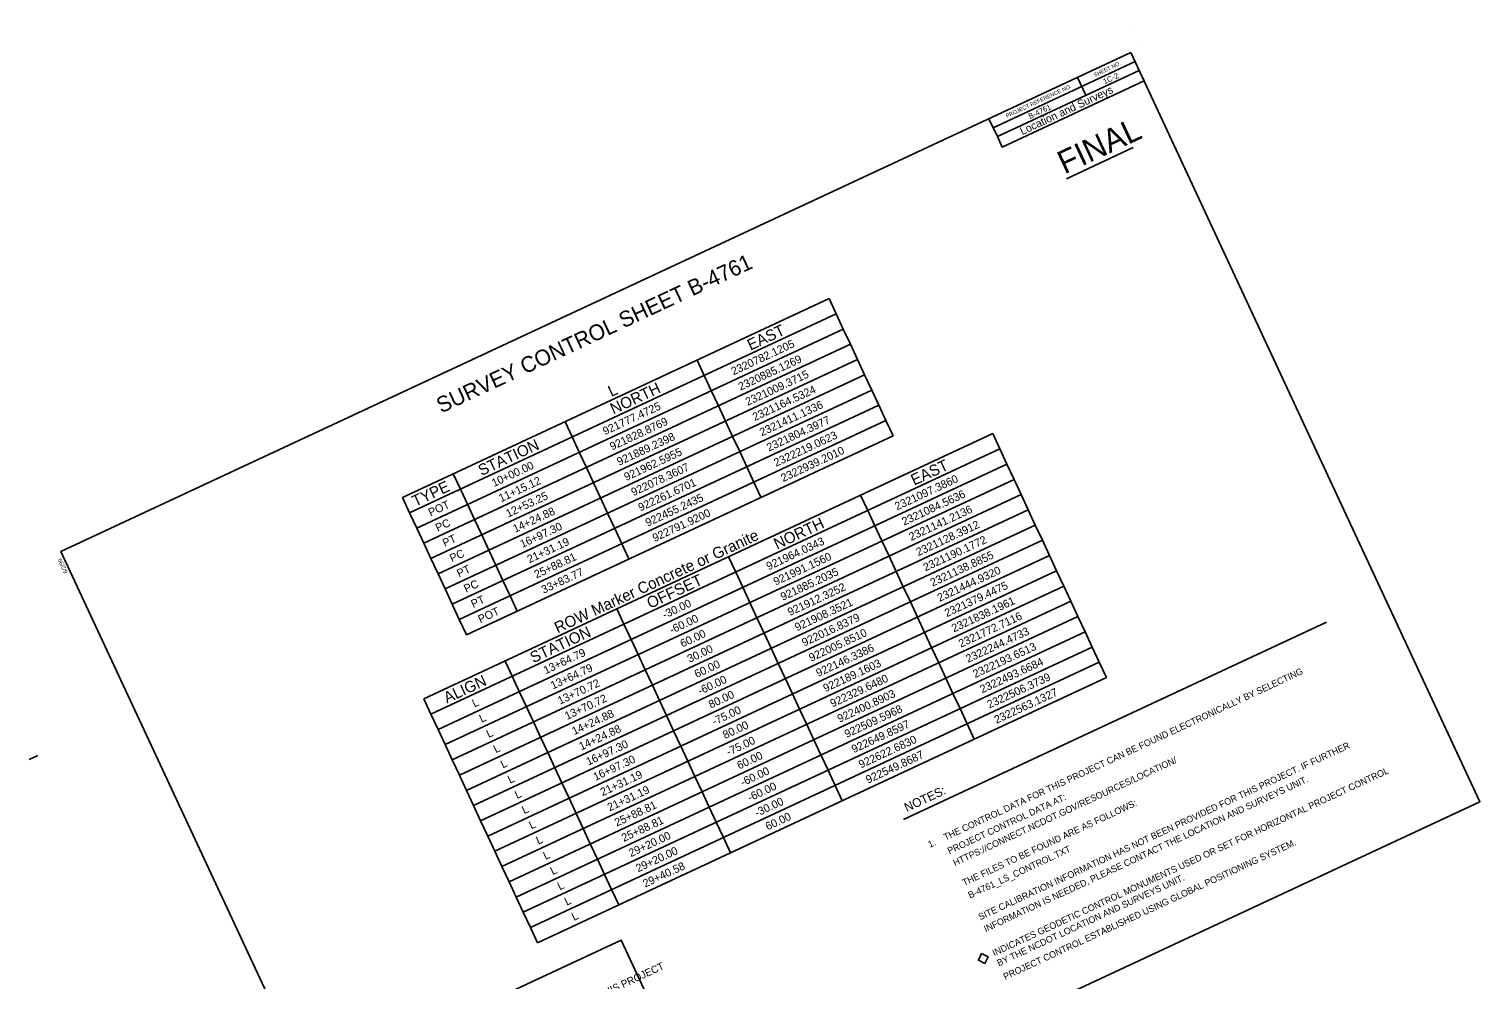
# Model space of a CAD drawing. Extents: x 2319517 to 2322650, y 921860 to 925282.
# Drawn here: x 2319517 to 2322650, y 923230 to 925282 of the extents above; entities that cross this region are included whole.
import ezdxf

# ---------------------------------------------------------------- set-up
doc = ezdxf.new("R2010")
doc.units = 0
for name, color, linetype in [('CTL Sheet Border CELL', 7, 'Continuous'), ('CTL Sheet Datum Description CELL', 7, 'Continuous'), ('CTL Sheet Notes CELL', 7, 'Continuous'), ('CTL Sheet Table Cell', 7, 'Continuous'), ('CTL Sheet Text', 7, 'Continuous'), ('CTL Supplemental Horizontal and Vertical CELL', 7, 'Continuous'), ('Sheet Sticker Preliminary CELL', 7, 'Continuous')]:
    doc.layers.add(name, color=color, linetype=linetype)

msp = doc.modelspace()

# ---------------------------------------------------------------- linework, layer by layer
at = {"layer": 'CTL Sheet Border CELL'}
for p, q in [((2321904.2, 925282.4), (2321904.2, 925282.4)), ((2321913.4, 925244.7), (2321913.4, 925244.7)), ((2321913.4, 925244.7), (2321913.4, 925244.7)), ((2321597, 925068.8), (2321905, 925212.4)), ((2321780.5, 925177.9), (2321798.5, 925139.4)), ((2321589.7, 925088.9), (2321607.7, 925050.4)), ((2319517.5, 923706.1), (2319536.7, 923715))]:
    msp.add_line(p, q, dxfattribs=at)
for points in [[(2321896, 925231.7), (2319586.4, 924155.2), (2320340, 922538.5), (2322649.5, 923615.1)], [(2321607.7, 925050.4), (2321913.9, 925193.2), (2321924.5, 925170.5), (2321618.2, 925027.8)]]:
    msp.add_lwpolyline(points, close=True, dxfattribs=at)
at = {"layer": 'CTL Sheet Datum Description CELL'}
msp.add_lwpolyline([(2320359.3, 922575.6), (2320153.7, 923016.8), (2320795.8, 923316.1), (2321001.5, 922874.9)], close=True, dxfattribs=at)
at = {"layer": 'CTL Sheet Notes CELL'}
msp.add_line((2321405.2, 923576.9), (2322318.1, 924002.4), dxfattribs=at)
at = {"layer": 'CTL Sheet Table Cell'}
for p, q in [((2320323.6, 924271.5), (2321244.6, 924700.8)), ((2321244.6, 924700.8), (2321259.9, 924667.9)), ((2320339, 924238.6), (2321259.9, 924667.9)), ((2321259.9, 924667.9), (2321275.2, 924635)), ((2320354.3, 924205.7), (2321275.2, 924635)), ((2321275.2, 924635), (2321290.6, 924602.1)), ((2320369.6, 924172.8), (2321290.6, 924602.1)), ((2321290.6, 924602.1), (2321305.9, 924569.2)), ((2320385, 924140), (2321305.9, 924569.2)), ((2320959.5, 924567.9), (2320974.8, 924535)), ((2321305.9, 924569.2), (2321321.2, 924536.3)), ((2320400.3, 924107.1), (2321321.2, 924536.3)), ((2320974.8, 924535), (2320990.2, 924502.1)), ((2321321.2, 924536.3), (2321336.6, 924503.4)), ((2320415.6, 924074.2), (2321336.6, 924503.4)), ((2320990.2, 924502.1), (2321005.5, 924469.2)), ((2321336.6, 924503.4), (2321351.9, 924470.5)), ((2320431, 924041.3), (2321351.9, 924470.5)), ((2321005.5, 924469.2), (2321020.8, 924436.4)), ((2321351.9, 924470.5), (2321367.2, 924437.7)), ((2320446.3, 924008.4), (2321367.2, 924437.7)), ((2320674.5, 924435), (2320689.8, 924402.2)), ((2321020.8, 924436.4), (2321036.2, 924403.5)), ((2321367.2, 924437.7), (2321382.5, 924404.8)), ((2320369.8, 923836.9), (2321597.7, 924409.3)), ((2320461.6, 923975.5), (2321382.5, 924404.8)), ((2321597.7, 924409.3), (2321613, 924376.4)), ((2320385.1, 923804.1), (2321613, 924376.4)), ((2320689.8, 924402.2), (2320705.1, 924369.3)), ((2321036.2, 924403.5), (2321051.5, 924370.6)), ((2321613, 924376.4), (2321628.3, 924343.5)), ((2320400.4, 923771.2), (2321628.3, 924343.5)), ((2320705.1, 924369.3), (2320720.5, 924336.4)), ((2321051.5, 924370.6), (2321066.8, 924337.7)), ((2321628.3, 924343.5), (2321643.7, 924310.6)), ((2320415.7, 923738.3), (2321643.7, 924310.6)), ((2320433.3, 924322.6), (2320448.6, 924289.7)), ((2320720.5, 924336.4), (2320735.8, 924303.5)), ((2321066.8, 924337.7), (2321082.2, 924304.8)), ((2321643.7, 924310.6), (2321659, 924277.7)), ((2320448.6, 924289.7), (2320463.9, 924256.8)), ((2320735.8, 924303.5), (2320751.1, 924270.6)), ((2321082.2, 924304.8), (2321097.5, 924271.9)), ((2320323.6, 924271.5), (2320339, 924238.6)), ((2320431.1, 923705.4), (2321659, 924277.7)), ((2320463.9, 924256.8), (2320479.3, 924223.9)), ((2320751.1, 924270.6), (2320766.5, 924237.7)), ((2321312.6, 924276.4), (2321327.9, 924243.5)), ((2321659, 924277.7), (2321674.3, 924244.9)), ((2320339, 924238.6), (2320354.3, 924205.7)), ((2320446.4, 923672.5), (2321674.3, 924244.9)), ((2320479.3, 924223.9), (2320494.6, 924191.1)), ((2320766.5, 924237.7), (2320781.8, 924204.8)), ((2321327.9, 924243.5), (2321343.3, 924210.7)), ((2321674.3, 924244.9), (2321689.6, 924212)), ((2320354.3, 924205.7), (2320369.6, 924172.8)), ((2320461.7, 923639.6), (2321689.6, 924212)), ((2320494.6, 924191.1), (2320509.9, 924158.2)), ((2320781.8, 924204.8), (2320797.1, 924171.9)), ((2321343.3, 924210.7), (2321358.6, 924177.8)), ((2321689.6, 924212), (2321705, 924179.1)), ((2320369.6, 924172.8), (2320385, 924140)), ((2320477.1, 923606.7), (2321705, 924179.1)), ((2320509.9, 924158.2), (2320525.3, 924125.3)), ((2320797.1, 924171.9), (2320812.4, 924139)), ((2321358.6, 924177.8), (2321373.9, 924144.9)), ((2321705, 924179.1), (2321720.3, 924146.2)), ((2320385, 924140), (2320400.3, 924107.1)), ((2320492.4, 923573.8), (2321720.3, 924146.2)), ((2320525.3, 924125.3), (2320540.6, 924092.4)), ((2321027.6, 924143.6), (2321042.9, 924110.7)), ((2321373.9, 924144.9), (2321389.3, 924112)), ((2321720.3, 924146.2), (2321735.6, 924113.3)), ((2320400.3, 924107.1), (2320415.6, 924074.2)), ((2320507.7, 923540.9), (2321735.6, 924113.3)), ((2320540.6, 924092.4), (2320555.9, 924059.5)), ((2321042.9, 924110.7), (2321058.2, 924077.8)), ((2321389.3, 924112), (2321404.6, 924079.1)), ((2321735.6, 924113.3), (2321751, 924080.4)), ((2320415.6, 924074.2), (2320431, 924041.3)), ((2320523.1, 923508), (2321751, 924080.4)), ((2320555.9, 924059.5), (2320571.2, 924026.6)), ((2321058.2, 924077.8), (2321073.6, 924044.9)), ((2321404.6, 924079.1), (2321419.9, 924046.2)), ((2321751, 924080.4), (2321766.3, 924047.5)), ((2320431, 924041.3), (2320446.3, 924008.4)), ((2320538.4, 923475.2), (2321766.3, 924047.5)), ((2320786.4, 924031.1), (2320801.7, 923998.3)), ((2321073.6, 924044.9), (2321088.9, 924012)), ((2321419.9, 924046.2), (2321435.3, 924013.3)), ((2321766.3, 924047.5), (2321781.6, 924014.6)), ((2320446.3, 924008.4), (2320461.6, 923975.5)), ((2320553.7, 923442.3), (2321781.6, 924014.6)), ((2320801.7, 923998.3), (2320817, 923965.4)), ((2321088.9, 924012), (2321104.2, 923979.1)), ((2321435.3, 924013.3), (2321450.6, 923980.4)), ((2321781.6, 924014.6), (2321797, 923981.7)), ((2320569.1, 923409.4), (2321797, 923981.7)), ((2320817, 923965.4), (2320832.4, 923932.5)), ((2321104.2, 923979.1), (2321119.5, 923946.2)), ((2321450.6, 923980.4), (2321465.9, 923947.5)), ((2321797, 923981.7), (2321812.3, 923948.8)), ((2320584.4, 923376.5), (2321812.3, 923948.8)), ((2321119.5, 923946.2), (2321134.9, 923913.3)), ((2321465.9, 923947.5), (2321481.2, 923914.6)), ((2321812.3, 923948.8), (2321827.6, 923915.9)), ((2320545.2, 923918.7), (2320560.5, 923885.8)), ((2320599.7, 923343.6), (2321827.6, 923915.9)), ((2320832.4, 923932.5), (2320847.7, 923899.6)), ((2321134.9, 923913.3), (2321150.2, 923880.4)), ((2321481.2, 923914.6), (2321496.6, 923881.8)), ((2321827.6, 923915.9), (2321843, 923883.1)), ((2320560.5, 923885.8), (2320575.8, 923852.9)), ((2320615, 923310.7), (2321843, 923883.1)), ((2320847.7, 923899.6), (2320863, 923866.7)), ((2321150.2, 923880.4), (2321165.5, 923847.6)), ((2321496.6, 923881.8), (2321511.9, 923848.9)), ((2320575.8, 923852.9), (2320591.2, 923820)), ((2320863, 923866.7), (2320878.3, 923833.8)), ((2321165.5, 923847.6), (2321180.9, 923814.7)), ((2321511.9, 923848.9), (2321527.2, 923816)), ((2320369.8, 923836.9), (2320385.1, 923804.1)), ((2320591.2, 923820), (2320606.5, 923787.2)), ((2320878.3, 923833.8), (2320893.7, 923800.9)), ((2321180.9, 923814.7), (2321196.2, 923781.8)), ((2321527.2, 923816), (2321542.6, 923783.1)), ((2320385.1, 923804.1), (2320400.4, 923771.2)), ((2320606.5, 923787.2), (2320621.8, 923754.3)), ((2320893.7, 923800.9), (2320909, 923768)), ((2321196.2, 923781.8), (2321211.5, 923748.9)), ((2321542.6, 923783.1), (2321557.9, 923750.2)), ((2320400.4, 923771.2), (2320415.7, 923738.3)), ((2320621.8, 923754.3), (2320637.2, 923721.4)), ((2320909, 923768), (2320924.3, 923735.1)), ((2321211.5, 923748.9), (2321226.9, 923716)), ((2320415.7, 923738.3), (2320431.1, 923705.4)), ((2320637.2, 923721.4), (2320652.5, 923688.5)), ((2320924.3, 923735.1), (2320939.7, 923702.2)), ((2321226.9, 923716), (2321242.2, 923683.1)), ((2320431.1, 923705.4), (2320446.4, 923672.5)), ((2320652.5, 923688.5), (2320667.8, 923655.6)), ((2320939.7, 923702.2), (2320955, 923669.3)), ((2320446.4, 923672.5), (2320461.7, 923639.6)), ((2320667.8, 923655.6), (2320683.1, 923622.7)), ((2320955, 923669.3), (2320970.3, 923636.5)), ((2321242.2, 923683.1), (2321257.5, 923650.2)), ((2320461.7, 923639.6), (2320477.1, 923606.7)), ((2320683.1, 923622.7), (2320698.5, 923589.8)), ((2320970.3, 923636.5), (2320985.7, 923603.6)), ((2321257.5, 923650.2), (2321272.9, 923617.3)), ((2320477.1, 923606.7), (2320492.4, 923573.8)), ((2320698.5, 923589.8), (2320713.8, 923556.9)), ((2320985.7, 923603.6), (2321001, 923570.7)), ((2320492.4, 923573.8), (2320507.7, 923540.9)), ((2321001, 923570.7), (2321016.3, 923537.8)), ((2320507.7, 923540.9), (2320523.1, 923508)), ((2320713.8, 923556.9), (2320729.1, 923524)), ((2321016.3, 923537.8), (2321031.7, 923504.9)), ((2320523.1, 923508), (2320538.4, 923475.2)), ((2320729.1, 923524), (2320744.5, 923491.1)), ((2320538.4, 923475.2), (2320553.7, 923442.3)), ((2320744.5, 923491.1), (2320759.8, 923458.2)), ((2320553.7, 923442.3), (2320569.1, 923409.4)), ((2320759.8, 923458.2), (2320775.1, 923425.4)), ((2320569.1, 923409.4), (2320584.4, 923376.5)), ((2320775.1, 923425.4), (2320790.5, 923392.5)), ((2320584.4, 923376.5), (2320599.7, 923343.6)), ((2320599.7, 923343.6), (2320615, 923310.7))]:
    msp.add_line(p, q, dxfattribs=at)
at = {"layer": 'CTL Supplemental Horizontal and Vertical CELL'}
msp.add_line((2321577.2, 923276.7), (2321577.2, 923276.7), dxfattribs=at)
msp.add_lwpolyline([(2321573.6, 923287.2), (2321587.8, 923280.3), (2321580.9, 923266.1), (2321566.7, 923273.1)], close=True, dxfattribs=at)
at = {"layer": 'Sheet Sticker Preliminary CELL'}
msp.add_line((2321756.9, 924959.5), (2321901, 925026.7), dxfattribs=at)

# ---------------------------------------------------------------- texts
at = {"layer": 'CTL Sheet Border CELL'}
for s, height, rotation, p in [('SHEET NO.', 8.49, 24.9913, (2321818.1, 925179)), ('1C-2', 12, 24.9913, (2321839.5, 925162.9)), ('PROJECT REFERENCE NO.', 8.494, 24.9913, (2321628.4, 925090.7)), ('Location and Surveys', 16.988, 24.9913, (2321661.4, 925053.3)), ('B-4761', 12, 24.9913, (2321678.1, 925087.9)), ('SURVEY CONTROL SHEET B-4761', 33.975, 24.9913, (2320407, 924452.7)), ('6/2/99', 8.92, 114.9913, (2319601.5, 924110.2))]:
    msp.add_text(s, height=height, rotation=rotation, dxfattribs=at).set_placement(p)
at = {"layer": 'CTL Sheet Datum Description CELL'}
msp.add_text('THE LOCALIZED COORDINATE SYSTEM DEVELOPED FOR THIS PROJECT', height=15.941, rotation=24.9913, dxfattribs=at).set_placement((2320205.1, 922935.5))
at = {"layer": 'CTL Sheet Notes CELL'}
for s, height, rotation, p in [('EAST', 24.19, 24.9913, (2321074.9, 924588.3)), ('L', 24.2, 24.9913, (2320774.3, 924488.2)), ('NORTH', 24.19, 24.9913, (2320779, 924450.4)), ('STATION', 24.19, 24.9913, (2320494.1, 924317.6)), ('EAST', 24.19, 24.9913, (2321428, 924296.9)), ('TYPE', 24.19, 24.9913, (2320351.3, 924251.1)), ('NORTH', 24.19, 24.9913, (2321132.1, 924158.9)), ('ROW Marker Concrete or Granite', 24.192, 24.9913, (2320658.5, 923978.2)), ('OFFSET', 24.19, 24.9913, (2320858.1, 924031.2)), ('STATION', 24.19, 24.9913, (2320606, 923913.7)), ('1.    THE CONTROL DATA FOR THIS PROJECT CAN BE FOUND ELECTRONICALLY BY SELECTING', 14.321, 24.9913, (2321462, 923515.4)), ('ALIGN', 24.19, 24.9913, (2320419.5, 923826.8)), ('SITE CALIBRATION INFORMATION HAS NOT BEEN PROVIDED FOR THIS PROJECT. IF FURTHER', 14.321, 24.9913, (2321570.7, 923358.9)), ('HTTPS://CONNECT.NCDOT.GOV/RESOURCES/LOCATION/', 14.321, 24.9913, (2321516.2, 923475.9)), ('INDICATES GEODETIC CONTROL MONUMENTS USED OR SET FOR HORIZONTAL PROJECT CONTROL', 14.321, 24.8861, (2321601, 923281.3)), ('INFORMATION IS NEEDED, PLEASE CONTACT THE LOCATION AND SURVEYS UNIT.', 14.321, 24.9913, (2321582.6, 923333.3)), ('NOTES:', 19.1, 24.8861, (2321412.2, 923592.7)), ('PROJECT CONTROL DATA AT:', 14.321, 24.9913, (2321504.2, 923501.6)), ('THE FILES TO BE FOUND ARE AS FOLLOWS:', 14.321, 24.9913, (2321536.2, 923433)), ('PROJECT CONTROL ESTABLISHED USING GLOBAL POSITIONING SYSTEM.', 14.321, 24.8861, (2321624.7, 923230.2)), ('B-4761_LS_CONTROL.TXT', 14.321, 24.9913, (2321548.7, 923406)), ('BY THE NCDOT LOCATION AND SURVEYS UNIT.', 14.321, 24.8861, (2321611, 923259.7))]:
    msp.add_text(s, height=height, rotation=rotation, dxfattribs=at).set_placement(p)
at = {"layer": 'CTL Sheet Text'}
for s, height, p in [('2320782.1205', 17.28, (2321038, 924534.9)), ('2320885.1269', 17.28, (2321053.4, 924502)), ('2321009.3715', 17.28, (2321068.7, 924469.1)), ('2321164.5324', 17.28, (2321084, 924436.3)), ('921777.4725', 17.28, (2320760.8, 924405.7)), ('2321411.1336', 17.28, (2321099.4, 924403.4)), ('921828.8769', 17.28, (2320776.1, 924372.8)), ('2321804.3977', 17.28, (2321114.7, 924370.5)), ('921889.2398', 17.28, (2320791.4, 924339.9)), ('2322219.0623', 17.28, (2321130, 924337.6)), ('921962.5955', 17.28, (2320806.8, 924307)), ('2322939.2010', 17.28, (2321145.4, 924304.7)), ('10+00.00', 17.28, (2320521, 924293.9)), ('922078.3607', 17.28, (2320822.1, 924274.1)), ('11+15.12', 17.28, (2320536.3, 924261)), ('922261.6701', 17.28, (2320837.4, 924241.2)), ('2321097.3860', 17.28, (2321391.1, 924243.5)), ('12+53.25', 17.28, (2320551.6, 924228.1)), ('922455.2435', 17.28, (2320852.8, 924208.3)), ('2321084.5636', 17.28, (2321406.5, 924210.6)), ('POT', 17.28, (2320384.4, 924230.2)), ('14+24.88', 17.28, (2320566.9, 924195.2)), ('2321141.2136', 17.28, (2321421.8, 924177.7)), ('PC ', 17.28, (2320399.7, 924197.4)), ('16+97.30', 17.28, (2320582.3, 924162.3)), ('922791.9200', 17.28, (2320868.1, 924175.4)), ('2321128.3912', 17.28, (2321437.1, 924144.8)), ('PT ', 17.28, (2320415, 924164.5)), ('21+31.19', 17.28, (2320597.6, 924129.4)), ('921964.0343', 17.28, (2321113.9, 924114.2)), ('2321190.1772', 17.28, (2321452.5, 924111.9)), ('PC ', 17.28, (2320430.4, 924131.6)), ('2321138.8855', 17.28, (2321467.8, 924079)), ('PT ', 17.28, (2320445.7, 924098.7)), ('25+88.81', 17.28, (2320612.9, 924096.6)), ('921991.1560', 17.28, (2321129.2, 924081.3)), ('2321444.9320', 17.28, (2321483.1, 924046.1)), ('PC ', 17.28, (2320461, 924065.8)), ('33+83.77', 17.28, (2320628.3, 924063.7)), ('921885.2035', 17.28, (2321144.5, 924048.4)), ('2321379.4475', 17.28, (2321498.5, 924013.2)), ('PT ', 17.28, (2320476.4, 924032.9)), ('921912.3252', 17.28, (2321159.9, 924015.5)), ('POT', 17.28, (2320491.7, 924000)), ('-30.00', 17.28, (2320889.6, 924009.7)), ('921908.3521', 17.28, (2321175.2, 923982.6)), ('2321838.1961', 17.28, (2321513.8, 923980.3)), ('-60.00', 17.28, (2320904.9, 923976.8)), ('922016.8379', 17.28, (2321190.5, 923949.8)), ('2321772.7116', 17.28, (2321529.1, 923947.4)), ('60.00', 17.28, (2320928, 923947.5)), ('922005.8510', 17.28, (2321205.8, 923916.9)), ('2322244.4733', 17.28, (2321544.4, 923914.5)), ('13+64.79', 17.28, (2320632.8, 923890)), ('30.00', 17.28, (2320943.3, 923914.6)), ('922146.3386', 17.28, (2321221.2, 923884)), ('2322193.6513', 17.28, (2321559.8, 923881.7)), ('13+64.79', 17.28, (2320648.2, 923857.1)), ('60.00', 17.28, (2320958.7, 923881.7)), ('922189.1603', 17.28, (2321236.5, 923851.1)), ('2322493.6684', 17.28, (2321575.1, 923848.8)), ('13+70.72', 17.28, (2320663.5, 923824.2)), ('-60.00', 17.28, (2320966.2, 923845.2)), ('922329.6480', 17.28, (2321251.8, 923818.2)), ('2322506.3739', 17.28, (2321590.4, 923815.9)), ('13+70.72', 17.28, (2320678.8, 923791.3)), ('80.00', 17.28, (2320989.3, 923815.9)), ('922400.8903', 17.28, (2321267.2, 923785.3)), ('2322563.1327', 17.28, (2321605.8, 923783)), ('L', 17.3, (2320478.9, 923818.2)), ('14+24.88', 17.28, (2320694.2, 923758.4)), ('-75.00', 17.28, (2320996.9, 923779.4)), ('922509.5968', 17.28, (2321282.5, 923752.4)), ('L', 17.3, (2320494.3, 923785.4)), ('14+24.88', 17.28, (2320709.5, 923725.5)), ('80.00', 17.28, (2321020, 923750.2)), ('922649.8597', 17.28, (2321297.8, 923719.5)), ('L', 17.3, (2320509.6, 923752.5)), ('16+97.30', 17.28, (2320724.8, 923692.7)), ('-75.00', 17.28, (2321027.6, 923713.7)), ('922622.6830', 17.28, (2321313.2, 923686.6)), ('L', 17.3, (2320524.9, 923719.6)), ('16+97.30', 17.28, (2320740.2, 923659.8)), ('60.00', 17.28, (2321050.7, 923684.4)), ('922549.8687', 17.28, (2321328.5, 923653.7)), ('L', 17.3, (2320540.2, 923686.7)), ('-60.00', 17.28, (2321058.2, 923647.9)), ('L', 17.3, (2320555.6, 923653.8)), ('21+31.19', 17.28, (2320755.5, 923626.9)), ('-60.00', 17.28, (2321073.6, 923615)), ('L', 17.3, (2320570.9, 923620.9)), ('21+31.19', 17.28, (2320770.8, 923594)), ('-30.00', 17.28, (2321088.9, 923582.1)), ('L', 17.3, (2320586.2, 923588)), ('25+88.81', 17.28, (2320786.2, 923561.1)), ('60.00', 17.28, (2321112, 923552.8)), ('L', 17.3, (2320601.6, 923555.1)), ('25+88.81', 17.28, (2320801.5, 923528.2)), ('L', 17.3, (2320616.9, 923522.2)), ('29+20.00', 17.28, (2320816.8, 923495.3)), ('L', 17.3, (2320632.2, 923489.3)), ('29+20.00', 17.28, (2320832.1, 923462.4)), ('L', 17.3, (2320647.6, 923456.5)), ('29+40.58', 17.28, (2320847.5, 923429.5)), ('L', 17.3, (2320662.9, 923423.6)), ('L', 17.3, (2320678.2, 923390.7)), ('L', 17.3, (2320693.6, 923357.8))]:
    msp.add_text(s, height=height, rotation=24.9913, dxfattribs=at).set_placement(p)
at = {"layer": 'Sheet Sticker Preliminary CELL'}
msp.add_text('FINAL', height=49.77, rotation=25.0046, dxfattribs=at).set_placement((2321752.6, 924968.5))

doc.saveas('drawing.dxf')
